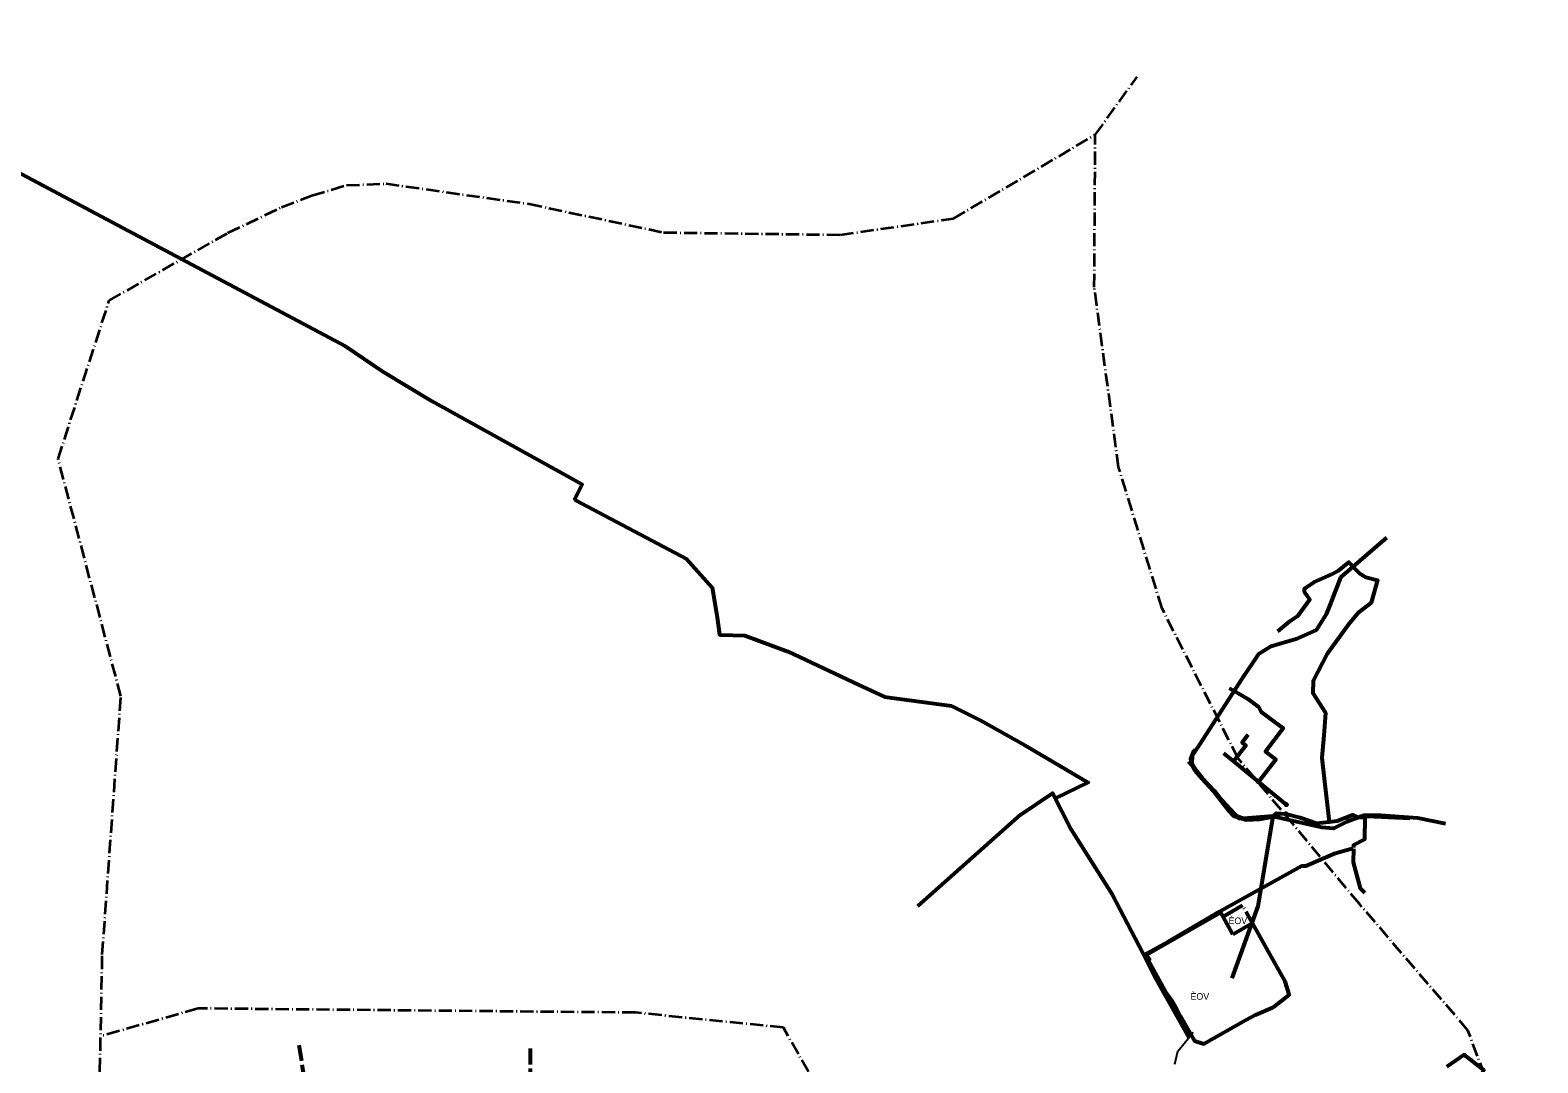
# Model space of a CAD drawing. Extents: x -650270 to -643402, y -1075206 to -1066807.
# Drawn here: x -647793 to -645515, y -1069270 to -1067709 of the extents above; entities that cross this region are included whole.
import ezdxf

# ---------------------------------------------------------------- set-up
doc = ezdxf.new("R2010")
doc.units = 0
doc.header["$LTSCALE"] = 4
doc.header["$PDMODE"] = 32
doc.header["$PDSIZE"] = 2
doc.linetypes.add('DOT_DASHED', pattern=[7.7, 5, -1.2, 0.3, -1.2])
doc.linetypes.add('LONG_DASHED', pattern=[7.5, 6, -1.5])
for name, color, linetype, lineweight in [('16', 7, 'Continuous', 25), ('17', 7, 'DOT_DASHED', 35), ('21', 7, 'Continuous', 53), ('22', 7, 'DOT_DASHED', 53), ('4', 7, 'Continuous', 53), ('43', 7, 'Continuous', 53), ('47', 7, 'Continuous', 40), ('48', 7, 'Continuous', 53), ('5', 7, 'Continuous', 53), ('51', 7, 'Continuous', 53)]:
    doc.layers.add(name, color=color, linetype=linetype, lineweight=lineweight)

msp = doc.modelspace()

# ---------------------------------------------------------------- linework, layer by layer
at = {"layer": '16'}
msp.add_lwpolyline([(-646062.988, -1069271.856), (-646058.427, -1069252.383), (-646047.044, -1069237.982), (-646035.66, -1069223.58)], dxfattribs=at)
at = {"layer": '17'}
for points in [[(-648163.245, -1069677.659), (-647956.36, -1069616.266), (-647792.66, -1069528.568), (-647711.796, -1069423.024), (-647687.185, -1069282.298), (-647683.669, -1069106.39), (-647655.542, -1068715.876), (-647750.47, -1068357.024), (-647673.122, -1068117.79), (-647493.814, -1068015.764), (-647412.95, -1067977.064), (-647367.244, -1067959.473), (-647314.919, -1067943.73), (-647255.446, -1067941.26), (-647038.873, -1067971.862), (-646835.475, -1068015.092), (-646568.272, -1068018.608), (-646397.754, -1067993.997), (-646183.288, -1067867.427), (-646120.196, -1067780.102)], [(-644568.435, -1070960.552), (-644606.234, -1070747.935), (-644654.246, -1070597.895), (-644792.283, -1070387.84), (-645046.599, -1070192.79), (-645228.623, -1070004.752), (-645232.28, -1069980.924), (-645262.713, -1069836.388), (-645315.002, -1069657.333), (-645409.031, -1069473.75), (-645471.738, -1069397.026), (-645547.224, -1069323.801), (-645594.94, -1069288.511), (-645620.197, -1069220.915), (-645784.301, -1069029.743), (-645967.439, -1068809.81), (-646082.481, -1068583.109), (-646148.037, -1068369.943), (-646184.835, -1068097.563), (-646183.288, -1067867.427)], [(-646584.549, -1071124.89), (-646410.298, -1070907.26), (-646232.358, -1070648.654), (-646054.418, -1070451.734), (-646014.085, -1070223.971), (-646011.713, -1070105.345), (-646127.967, -1070010.443), (-646431.058, -1069900.12), (-646583.457, -1069759.191), (-646548.91, -1069578.56), (-646571.479, -1069363.822), (-646654.434, -1069216.7), (-646878.202, -1069194.008), (-647539.001, -1069187.705), (-647686.136, -1069229.838)]]:
    msp.add_lwpolyline(points, dxfattribs=at)
at = {"layer": '21'}
msp.add_lwpolyline([(-645975.48, -1069075.71), (-645990.13, -1069049.301), (-645993.848, -1069042.589), (-646106.311, -1069107.251), (-646101.57, -1069113.74), (-646103.591, -1069114.91), (-646087.52, -1069143.7), (-646075.88, -1069165.21), (-646067.71, -1069176.01), (-646060.75, -1069188.02), (-646054.873, -1069199.282), (-646054.678, -1069199.2), (-646042, -1069221.33), (-646033.271, -1069236.507), (-646019.24, -1069241.19), (-645955.1, -1069204.88), (-645941.385, -1069197.185), (-645915.71, -1069186.03), (-645913.47, -1069185.07), (-645890.317, -1069166.97), (-645893.49, -1069156.53), (-645896.35, -1069147.12), (-645903.35, -1069134.27), (-645924.02, -1069097.485), (-645945.685, -1069058.929)], close=True, dxfattribs=at)
at = {"layer": '22'}
msp.add_lwpolyline([(-645945.685, -1069058.929), (-645960.67, -1069032.26), (-645975.4, -1069040.78), (-645990.13, -1069049.3)], dxfattribs=at)
at = {"layer": '4'}
msp.add_line((-645841.148, -1068914.276), (-645915.285, -1068897.386), dxfattribs=at)
for points in [[(-645743.059, -1068476.379), (-645812.854, -1068536.591), (-645828.899, -1068578.338), (-645834.514, -1068591.986), (-645849.757, -1068616.071), (-645880.242, -1068629.719), (-645917.947, -1068640.958), (-645937.201, -1068653.001), (-645959.664, -1068686.72)], [(-645957.124, -1068682.702), (-646025.934, -1068788.829), (-646037.089, -1068805.562), (-646037.554, -1068818.111), (-646031.512, -1068830.196), (-645965.745, -1068900.792), (-645915.165, -1068896.655)], [(-645915.285, -1068897.386), (-645937.63, -1069033.023), (-645976.999, -1069141.866)], [(-645654.382, -1068908.587), (-645695.934, -1068900.379), (-645752.035, -1068896.262), (-645777.633, -1068896.262), (-645803.3, -1068905.491), (-645823.286, -1068915.717), (-645841.148, -1068914.276)]]:
    msp.add_lwpolyline(points, dxfattribs=at)
at = {"layer": '43', "linetype": 'LONG_DASHED'}
for p, q in [((-647386.783, -1069243.021), (-647337.628, -1069543.417)), ((-647037.18, -1069248.217), (-647037.18, -1069545.391))]:
    msp.add_line(p, q, dxfattribs=at)
at = {"layer": '48'}
msp.add_line((-645981.259, -1068703.511), (-645967.385, -1068711.482), dxfattribs=at)
for points in [[(-645907.362, -1068617.782), (-645889.568, -1068602.564), (-645876.887, -1068593.676), (-645859.253, -1068569.609), (-645867.265, -1068558.085), (-645867.406, -1068553.241), (-645853.323, -1068543.361), (-645827.027, -1068531.946), (-645816.331, -1068526.326), (-645800.023, -1068513.497), (-645783.355, -1068530.492), (-645774.539, -1068535.948), (-645757.012, -1068540.689), (-645766.363, -1068574.93), (-645786.158, -1068590.097), (-645800.925, -1068607.467), (-645832.749, -1068651.725), (-645854.306, -1068692.565), (-645854.5, -1068711.115), (-645835.59, -1068740.909), (-645838.212, -1068775.033), (-645840.835, -1068809.156), (-645836.304, -1068849.486), (-645830.009, -1068905.531), (-645817.671, -1068904.145), (-645794.596, -1068895.246), (-645786.942, -1068898.462), (-645775.928, -1068898.705), (-645776.729, -1068932.362), (-645793.148, -1068940.923), (-645793.235, -1068944.604)], [(-645967.385, -1068711.482), (-645952.849, -1068719.994), (-645936.764, -1068731.758), (-645932.629, -1068739.558), (-645912.463, -1068754.396), (-645899.435, -1068764.348), (-645926.111, -1068799.268), (-645910.63, -1068811.261), (-645936.673, -1068845.097)], [(-645953.001, -1068774.242), (-645961.611, -1068785.749), (-645955.699, -1068790.172), (-645974.573, -1068814.129)], [(-645953.001, -1068774.242), (-645961.611, -1068785.749), (-645955.699, -1068790.172), (-645974.573, -1068814.129), (-645954.496, -1068830.434), (-645936.673, -1068845.097), (-645894.69, -1068879.637)], [(-646035.717, -1068796.973), (-646034.272, -1068798.019), (-646039.344, -1068810.269), (-646038.415, -1068815.963), (-646033.439, -1068824.717), (-646021.705, -1068839.115), (-646003.913, -1068858.5), (-645981.578, -1068887.109), (-645974.499, -1068895.164), (-645955.122, -1068901.555), (-645935.448, -1068900.633), (-645914.39, -1068896.88), (-645909.484, -1068892.743), (-645895.621, -1068893.663), (-645895.621, -1068893.657), (-645873.598, -1068899.269), (-645848.914, -1068907.655), (-645830.009, -1068905.531)], [(-645989.585, -1068801.938), (-645974.573, -1068814.129), (-645954.496, -1068830.434), (-645936.673, -1068845.097), (-645894.69, -1068879.637)], [(-646451.322, -1069032.874), (-646295.932, -1068894.5), (-646248.016, -1068862.258), (-646220.085, -1068916.892), (-646157.557, -1069015.41), (-646111.432, -1069104.078), (-646092.013, -1069143.037), (-646041.918, -1069231.497)], [(-645708.173, -1068900.605), (-645772.413, -1068897.59), (-645775.928, -1068898.705)], [(-645793.282, -1068946.603), (-645793.758, -1068966.676), (-645783.039, -1069005.779), (-645775.967, -1069013.041)], [(-645552.068, -1069638.526), (-645642.407, -1069592.458), (-645649.87, -1069590.965), (-645728.088, -1069578.714), (-645803.181, -1069570.441), (-645810.478, -1069572.033), (-645787.737, -1069536.624), (-645752.519, -1069500.102), (-645720.378, -1069461.316), (-645684.581, -1069417.092), (-645648.533, -1069373.739), (-645628.035, -1069340.99), (-645596.435, -1069280.712), (-645626.154, -1069257.704), (-645652.038, -1069275.918)]]:
    msp.add_lwpolyline(points, dxfattribs=at)
for p in [(-645936.673, -1068845.097), (-645895.621, -1068893.657), (-645894.69, -1068879.637)]:
    msp.add_point(p, dxfattribs=at)
at = {"layer": '5'}
msp.add_lwpolyline([(-646042.712, -1068814.269), (-646037.393, -1068820.191), (-646034.433, -1068825.398), (-646022.613, -1068839.901), (-646004.83, -1068859.276), (-645981.354, -1068889.132), (-645974.241, -1068896.513), (-645955.287, -1068902.764), (-645935.315, -1068901.828), (-645913.015, -1068897.854), (-645909.246, -1068894.676), (-645904.052, -1068894.564), (-645903.455, -1068894.651)], dxfattribs=at)
at = {"layer": '51'}
for points in [[(-648215.035, -1067709.37), (-647316.251, -1068186.867), (-647259.835, -1068225.098), (-647186.21, -1068269.45), (-646980.7, -1068383.53), (-646959.293, -1068395.4), (-646959.185, -1068396.415), (-646969.622, -1068417.688), (-646968.614, -1068419.426), (-646801.035, -1068508.24), (-646762.42, -1068551.73), (-646754.632, -1068597.002), (-646750.967, -1068622.408), (-646749.447, -1068623.2), (-646712.964, -1068624.297), (-646647.976, -1068648.366), (-646541.222, -1068698.651), (-646502.045, -1068716.94), (-646453.105, -1068723.49), (-646400.555, -1068730.38)], [(-646400.555, -1068730.38), (-646357.388, -1068751.896), (-646289.907, -1068789.892), (-646249.624, -1068813.51), (-646193.946, -1068846.371), (-646243.838, -1068870.431)], [(-645794.219, -1068945.883), (-645820.762, -1068953.606), (-645865.144, -1068972.751), (-645871.882, -1068972.89), (-645994.939, -1069041.006), (-646073.429, -1069086.912), (-646109.842, -1069107.217)]]:
    msp.add_lwpolyline(points, dxfattribs=at)

# ---------------------------------------------------------------- texts
at = {"layer": '47'}
for p in [(-645982.021, -1069060.206), (-646039.435, -1069174.524)]:
    msp.add_text('ÈOV', height=10, dxfattribs=at).set_placement(p)

doc.saveas('drawing.dxf')
